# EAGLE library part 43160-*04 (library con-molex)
SDA-43160 Connector Source: http://www.molex.com/pdm_docs/sd/431601306_sd.pdf
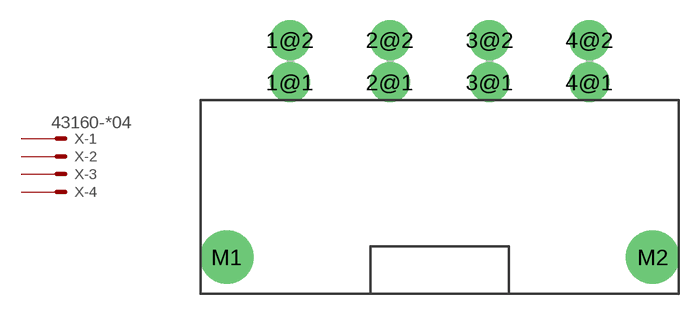
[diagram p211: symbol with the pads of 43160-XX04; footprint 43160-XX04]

Designator prefix X; gates -1=MV2 -2=M2 -3=M2 -4=M2

## 43160-1104 (MF: WALDOM/MOLEX; MPN: 43160-1104; OC_FARNELL: unknown; OC_NEWARK: 54H0257), 43160-1204 (OC_FARNELL: unknown; OC_NEWARK: unknown), 43160-1304 (MPN: 43160-1304; OC_FARNELL: unknown; OC_NEWARK: 92M1482), 43160-1404 (OC_FARNELL: unknown; OC_NEWARK: unknown), 43160-3104 (MF: FARNELL; MPN: 43160-3104; OC_FARNELL: 3293051; OC_NEWARK: 19J5462), 43160-3204 (OC_FARNELL: unknown; OC_NEWARK: unknown), 43160-5104 (MPN: 43160-5104; OC_FARNELL: unknown; OC_NEWARK: 92M1495), 43160-5204 (OC_FARNELL: unknown; OC_NEWARK: unknown), 43160-5304 (MPN: 43160-5304; OC_FARNELL: unknown; OC_NEWARK: 92M1500), 43160-5404 (OC_FARNELL: unknown; OC_NEWARK: unknown), 43160-7304 (MPN: 43160-7304; OC_FARNELL: unknown; OC_NEWARK: 92M1509), 43160-7404 (OC_FARNELL: unknown; OC_NEWARK: unknown)  [43160-XX04]
1@1  -1:S  pas
1@2  -1:S  pas
2@1  -2:S  pas
2@2  -2:S  pas
3@1  -3:S  pas
3@2  -3:S  pas
4@1  -4:S  pas
4@2  -4:S  pas

## Footprint 43160-XX04 (pad centres in mm)
SDA-43160 Connector Source: http://www.molex.com/pdm_docs/sd/431601306_sd.pdf
drill 1.8 pad 3 round: 1@1 -11.235,0; 1@2 -11.235,3.18; 2@1 -3.745,0; 2@2 -3.745,3.18; 3@1 3.745,0; 3@2 3.745,3.18; 4@1 11.235,0; 4@2 11.235,3.18
drill 3 pad 3.4 round: M1 -15.985,-13.13; M2 15.985,-13.13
